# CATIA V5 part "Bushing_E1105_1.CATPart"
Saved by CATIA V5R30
Part number: Vodici_pouzdro_15-17
Nomenclature: E1105/15-17
Description: MEUSBURGER
Property "Material": "2.0598"
Property "HeatTreat": "200HB"
Publications: "DrillHole", "Base"
Bounding box of the stored display mesh (mm): x -12.495 to 12.495, y -12.495 to 12.495, z -6 to 17
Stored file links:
  E:\Bakalarka\Model\Forma_v7\Bushing_E1105_1.CATPart
  E:\dev\MoldDesign\intel_a\startup\components\MoldCatalog\Bushing\Meusburger\Bushing_E1105\TableE1105.txt
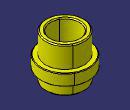
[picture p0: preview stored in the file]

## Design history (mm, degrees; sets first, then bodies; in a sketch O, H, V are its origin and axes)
Parameters
  Ref = "E1105/15-17" {design table}
  InD = 15 mm {design table}
  L1 = 17 mm {design table}
  L3 = 6 mm {design table}
  L5 = 6 mm {design table}
  L13 = 2.5 mm {design table}
  D1 = 20 mm {design table}
  D2 = 15 mm {design table}
  D3 = 25 mm {design table}
  L0 = 23 mm {design table}
  F = 0.3 mm {design table}
  F1 = 0.5 mm {design table}
  L2 = 23 mm {design table}
  D2a = 15.5 mm {design table}
  L6 = 0 mm {design table}
  k_d3 = 26 mm {design table}
  k_l3 = 6.3 mm {design table}
  k_I5 = 27 mm {design table}
  Mat = "2.0598" {design table}
  HeatTreat = "200HB" {design table}
  DrillHole_Length = 225 mm
  L = 17 mm {= L1}
  SupplierRef = "Meusburger 2017"
  BmpRef = "F_MldBushing_InD_L1_"
Set1 "BaseBody"
  Point1 "Base": (0, 0, 0)
  Plane1: type Offset, RefPlane xy-plane, Offset 225 {= DrillHole_Length}, reversed
Body1 "PartBody" (main body)
  Sketch1 on yz-plane, origin (0, 0, 0), H (0, 1, 0), V (0, 0, 1)
    point P1 (10, -6)
    line L1 (10, -6) -> (7.5, -6)
    point P2 (7.5, -6)
    line L2 (7.5, -6) -> (7.5, 17)
    line L3 (7.5, 17) -> (10, 17)
    point P4 (10, 17)
    point P5 (10, 17)
    line L4 (10, 17) -> (10, 6)
    line L5 (10, 6) -> (12.5, 6)
    line L6 (12.5, 6) -> (12.5, 0)
    line L7 (12.5, 0) -> (10, 0)
    point P9 (10, 0)
    point P10 (10, -6)
    point P11 (0, 17)
    axis line L8 (0, 17) -> (0, -6)
    point P12 (0, -6)
    line L9 (10, -6) -> (10, 0)
    point P13 (10, 0)
    point P14 (7.5, -6)
    point P15 (7.5, -6)
    distance L6 L8 = 12.5 {= D3 /2}
    length L6 = 6 {= L3}
    distance P10 L7 = 6 {= L5}
    distance L2 L8 = 7.5 {= D2 /2}
    distance P4 L8 = 10 {= D1 /2}
    length L2 = 23 {= L0}
    horizontal: L1 H, L3 H, L5 H
    vertical: L2 V, L4 V, L6 V, L9 V
    coincidence: L8 V, H L7, P1 P10, P13 H, P9 P13, P5 P4, L9 L4, P15 L1, P2 P15, P14 P2, P11 L3, P12 L1
  Shaft1: profile Sketch1, axis Sketch1.L8, angle 360
  Sketch2 on face of Shaft1 from Sketch1.L1, origin (0, 0, -10), H (1, 0, 0), V (0, -1, 0)
    point P1 (0, 0)
    reference projected point E1 (0, 0) from Point1
    coincidence: E1 P1
  Hole1 "Hole.3": placed by Sketch2, at (0, 0, -10) direction (0, 0, 1), diameter 15.5 {= D2a}, depth 1, deactivated
  Chamfer1: length 0.5 {= F1}, second length 0.5 {= F1}, on edge [face of Shaft1 from Sketch1.L9 | face of Shaft1 from Sketch1.L1]; edge [face of Shaft1 from Sketch1.L1 | face of Shaft1 from Sketch1.L2]; edge [face of Shaft1 from Sketch1.L3 | face of Shaft1 from Sketch1.L4]; edge [face of Shaft1 from Sketch1.L2 | face of Shaft1 from Sketch1.L3]
  Chamfer2: length 0.3 {= F}, second length 0.3 {= F}, on edge [face of Shaft1 from Sketch1.L6 | face of Shaft1 from Sketch1.L7]; edge [face of Shaft1 from Sketch1.L5 | face of Shaft1 from Sketch1.L6]
  Chamfer3: length 0.5 {= F1}, second length 0.5 {= F1}, on edge [face of Shaft1 from Sketch1.L1 | face of Hole1]; edge [face of Shaft1 from Sketch1.L9 | face of Shaft1 from Sketch1.L1]; edge [face of Shaft1 from Sketch1.L3 | face of Shaft1 from Sketch1.L4]; edge [face of Shaft1 from Sketch1.L2 | face of Shaft1 from Sketch1.L3], deactivated
  Chamfer4: length 0.3 {= F}, second length 0.3 {= F}, on edge [face of Shaft1 from Sketch1.L5 | face of Shaft1 from Sketch1.L6]; edge [face of Shaft1 from Sketch1.L6 | face of Shaft1 from Sketch1.L7], deactivated
Body2 "DrillHole"
  Sketch3 on xy-plane, origin (11.5957, -1.1405, 0), H (1, 0, 0), V (0, 1, 0)
    point P1 (-11.5957, 1.1405)
    reference projected circle E1 centre (-11.5957, 1.1405) radius 7.5 from edge [face of Shaft1 from Sketch1.L2 | face of Shaft1 from Sketch1.L3]
    concentricity: P1 E1
  Hole2 "Hole.1": placed by Sketch3, at (0, 0, 0) direction (0, 0, 1), diameter 20 {= D1}, depth 17 {= L1}, counterbore diameter 26 {= k_d3}, counterbore depth 6.3 {= k_l3}
  Sketch4 on Plane1, origin (0, 0, -225), H (1, 0, 0), V (0, 1, 0)
    point P1 (0, 0)
    reference projected circle E1 centre (0, 0) radius 10 from edge [face of Hole2 | face of Hole2]
    concentricity: E1 P1
  Hole3 "Hole.2": placed by Sketch4, at (0, 0, -225) direction (0, 0, 1), diameter 20 {= D1}, depth 225 {= DrillHole_Length}
Relations
  design table "TableE1105", configuration 23, drives Ref, InD, L1, L3, L5, L13, D1, D2, D3, L0, F, F1, L2, D2a, L6, k_d3, k_l3, k_I5, Mat, HeatTreat
  rule "Hole_activity":
    If (L0-L2) == 0mm
    {
    	Hole1.Activity=false
    	Sketch2.Activity =false
    	Hole1.Depth=1mm
    	Chamfer1.Activity = true
    	Chamfer2.Activity =true
    	Chamfer3.Activity = false
    	Chamfer4.Activity = false
    }
    Else
    {
    	Hole1.Activity=true
    	Sketch2.Activity =true
    	Hole1.Depth=L0-L2
    	Chamfer1.Activity = false
    	Chamfer2.Activity =false
    	Chamfer3.Activity = true
    	Chamfer4.Activity = true
    }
